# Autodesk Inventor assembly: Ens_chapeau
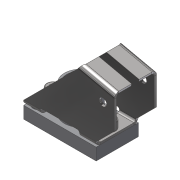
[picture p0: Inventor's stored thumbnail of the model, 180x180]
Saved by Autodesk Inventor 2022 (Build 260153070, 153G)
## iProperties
Created: 2018-06
Part Number: Ens_chapeau
Material: Générique
Document SubType Name: Assembly
Designer: Fabian Perrée
Mass: 105.136 g
Surface Area: 173.547 cm^2
Volume: 19.7524 cm^3
Density: 5.32267 g/cm^3
Author: Fabian Perrée
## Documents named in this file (5)
- C:\Users\Fabian\Google Drive\01_Giup\01_Clients\07_ENI\Manuscrit\Fichiers_exercice\Chapitre_06\Exercice_de_fin_de_chapitre\Exercice_fin_de_chapitre_solution\Ens_chapeau.iam
- C:\Users\Fabian\Google Drive\01_Giup\01_Clients\07_ENI\Manuscrit\Fichiers_exercice\CC\fr-FR\ISO 4762(2)\ISO 4762 - M5 x 8ISO.ipt
- C:\Users\Fabian\Google Drive\01_Giup\01_Clients\07_ENI\Manuscrit\Fichiers_exercice\Chapitre_06\Exercice_de_fin_de_chapitre\Composants\Etrier_tole.ipt
- C:\Users\Fabian\Google Drive\01_Giup\01_Clients\07_ENI\Manuscrit\Fichiers_exercice\Chapitre_06\Exercice_de_fin_de_chapitre\Composants\Chapeau_capteur.ipt
- C:\Users\Fabian\Google Drive\01_Giup\01_Clients\07_ENI\Manuscrit\Fichiers_exercice\Chapitre_06\Exercice_de_fin_de_chapitre\Composants\Bille_18.ipt
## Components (5 placed, 4 different names)
1. Etrier_tole:1 — Logement:3, Logement:4
2. Chapeau_capteur:1 — Logement:3, Logement:4
3. Bille_18:1
4. ISO 4762 M5 x 8:1
5. ISO 4762 M5 x 8:2
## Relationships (2: Insert 2)
- Logement:3 [Insert]: Etrier_tole:1 ↔ Chapeau_capteur:1
- Logement:4 [Insert]: Etrier_tole:1 ↔ Chapeau_capteur:1
